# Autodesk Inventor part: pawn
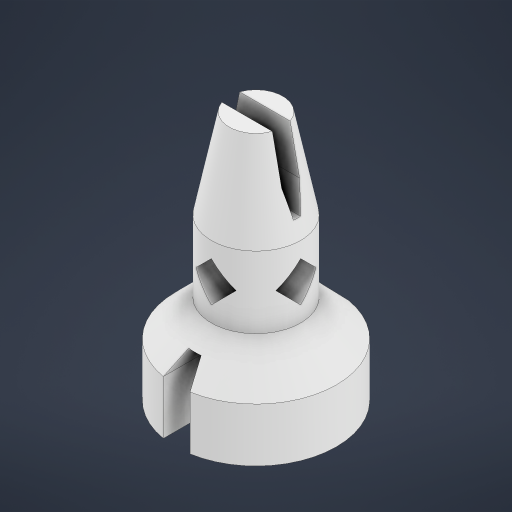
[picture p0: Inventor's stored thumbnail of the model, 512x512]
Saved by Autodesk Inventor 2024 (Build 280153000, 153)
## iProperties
Created: 2025-07
Part Number: pawn
Material: ABS Plastic
Document SubType Name: Modeling
Designer: acer
Density: 1.06 g/cm^3
Appearance: Smooth - White
Author: acer
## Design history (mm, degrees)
sketch "Sketch1"
  geometry: L1 (0, 0)-(0, 9); L2 (0, 0)-(28, 0); L3 (0, 9)-(6, 9); L4 (6, 9)-(6, 5); L5 (6, 5)-(18, 5); L6 (28, 0)-(28, 3); L7 (28, 3)-(18, 5)
  constraints: 14 end point, 2 horizontal, 2 perpendicular, 2 vertical
  dimensions: "d0" = 9 distance of L1.start L1.end; "d1" = 28 distance of L1.start L2.end; "d2" = 6 distance of L1.end L3.end; "d3" = 4 distance of L3.end L4.end; "d4" = 12 distance of L4.end L5.end; "d5" = 3 distance of L2.end L6.end
revolve "Revolution1" sketch "Sketch1" stored, may be unused: angle "d6" = 90 deg
chamfer "Chamfer1" distance "d7" = 4; stored, may be unused: second distance "d8" = 2, angle "d9" = 45 deg
sketch "Sketch2"
  geometry: L1 (18, -5)-(18, 5) reference; L2 (10, 5)-(10, -5) reference; L3 (18, 5)-(10, 5); L4 (10, 5)-(10, -5); L5 (10, -5)-(18, -5); L6 (18, -5)-(18, 5); L7 (14, 2.25)-(11.75, 0); L8 (11.75, 0)-(14, -2.25); L9 (14, -2.25)-(16.25, 0); L10 (16.25, 0)-(14, 2.25); A1 r 2.25 centre (14, 0) between (14, 2.25) and (11.75, 0); 1 further point
  constraints: 16 end point, 4 perpendicular, 4 point on circle, 2 parallel, 1 centre point, 1 horizontal
  dimensions: "d10" = 4.5 diameter of A1
extrude "Extrusion1" cut sketch "Sketch2" distance "d11" = 10; taper "d13" = 0 deg; dims "d12" = 10, "d14" = 0
sketch "Sketch3"
  geometry: L1 (5, 18)-(-5, 18) reference; L2 (5, 10)-(5, 18) reference; L3 (-5, 18)-(5, 18); L4 (5, 18)-(5, 10); L5 (5, 10)-(-5, 10); L6 (-5, 10)-(-5, 18); L7 (-4.465, 14)-(4.465, 14) reference; L8 (-2.25, 14)-(0, 11.75); L9 (0, 11.75)-(2.25, 14); L10 (2.25, 14)-(0, 16.25); L11 (0, 16.25)-(-2.25, 14); A1 r 2.25 centre (0, 14) between (-2.25, 14) and (0, 11.75); 1 further point
  constraints: 16 end point, 4 point on circle, 3 perpendicular, 3 point on line, 2 parallel, 1 centre point, 1 horizontal, 1 midpoint
extrude "Extrusion2" cut sketch "Sketch3" distance "d15" = 10; taper "d17" = 0 deg; dims "d16" = 5, "d18" = 0
sketch "Sketch4"
  geometry: L1 (-5, 10)-(5, 10) reference; L2 (0, 10)-(0, 0); L3 (9, 0)-(-9, 0) reference; L4 (-1.5, 10)-(1.5, 10); L5 (1.5, 10)-(1.5, 0); L6 (1.5, 0)-(-1.5, 0); L7 (-1.5, 0)-(-1.5, 10); L8 (-1.5, 10)-(1.5, 0); L9 (1.5, 10)-(-1.5, 0); L10 (0, 10)-(-1.5, 6); L11 (9, 6)-(-9, 6) reference; L12 (0, 10)-(1.5, 6); 2 further points
  constraints: 18 end point, 5 point on line, 4 midpoint, 2 parallel, 1 horizontal, 1 perpendicular, 1 vertical
  dimensions: "d19" = 3 distance of L5.end L6.end
extrude "Extrusion3" cut sketch "Sketch4" distance "d20" = 10; taper "d22" = 0 deg; dims "d21" = 10, "d23" = 0
chamfer "Chamfer2" distance "d24" = 2; stored, may be unused: second distance "d25" = 2, angle "d26" = 45 deg
sketch "Sketch5"
  geometry: L1 (18, -5)-(18, 5) reference; L2 (38, -1)-(18, -1); L3 (18, -1)-(18, 1); L4 (18, 1)-(38, 1); L5 (38, 1)-(38, -1); L6 (28, -3)-(28, 3) reference; L7 (38, -1)-(18, 1); L8 (18, -1)-(38, 1); L9 (18, -1)-(23, -1); L10 (18, 0)-(23, -1); L11 (18, 0)-(23, 1); 4 further points
  constraints: 18 end point, 4 midpoint, 3 point on line, 2 parallel, 1 horizontal, 1 perpendicular
  dimensions: "d27" = 2 distance of L2.end L3.end; "d28" = 5 distance of L2.end L9.end
extrude "Extrusion4" cut sketch "Sketch5" distance "d29" = 10; taper "d31" = 0 deg; dims "d30" = 8, "d32" = 0
chamfer "Chamfer3" distance "d33" = 2; stored, may be unused: second distance "d34" = 2, angle "d35" = 45 deg
body "Solid1"
